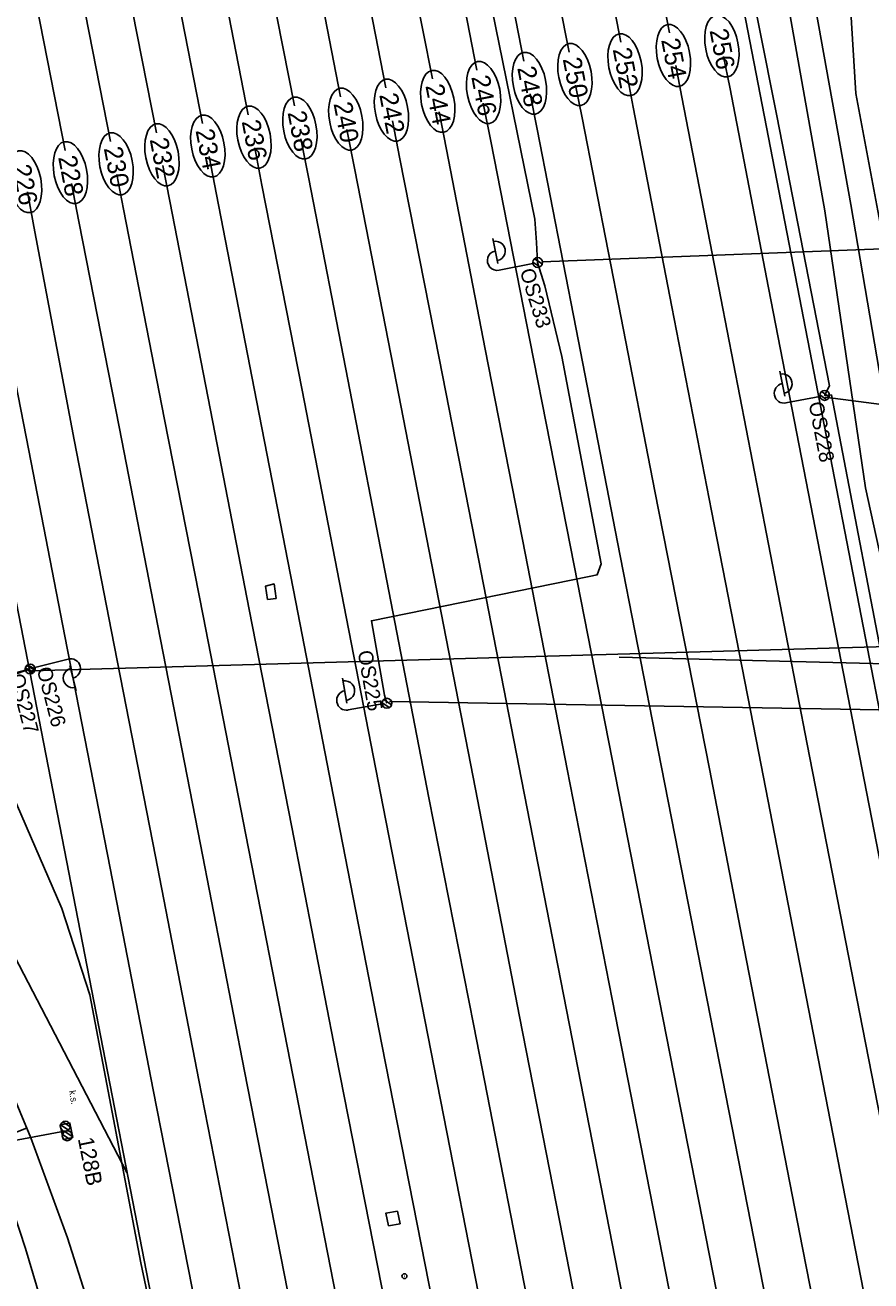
# Model space of a CAD drawing. Extents: x -545846 to -545044, y -1122650 to -1119108.
# Drawn here: x -545572.5 to -545486.4, y -1119708.7 to -1119580.9 of the extents above; entities that cross this region are included whole.
import ezdxf

# ---------------------------------------------------------------- set-up
doc = ezdxf.new("R2010")
doc.units = 0
for name, color, linetype in [('osvětlené plochy-hodnota-obrys', 7, 'Continuous'), ('Vrstva 1', 7, 'Continuous'), ('Vrstva 11 - Trakce', 7, 'Continuous'), ('Vrstva 12', 7, 'Continuous'), ('Vrstva 12 - Trakce zaklady', 7, 'Continuous'), ('Vrstva 25', 7, 'Continuous'), ('Vrstva 26', 7, 'Continuous'), ('Vrstva 50', 7, 'Continuous'), ('Vrstva 51', 7, 'Continuous'), ('Vrstva 62', 7, 'Continuous'), ('Vrstva 63', 7, 'Continuous'), ('Vrstva 7', 7, 'Continuous')]:
    doc.layers.add(name, color=color, linetype=linetype)

msp = doc.modelspace()

# ---------------------------------------------------------------- linework, layer by layer
at = {"layer": 'osvětlené plochy-hodnota-obrys'}
msp.add_line((-545562.16, -1119697.71), (-545631.88, -1119563.68), dxfattribs=at)
for points in [[(-545520.97, -1119506.47), (-545505.64, -1119546.72), (-545397.93, -1120102.85)], [(-545441.66, -1120319.91), (-545444.67, -1120302.28), (-545584.85, -1119581.02)]]:
    msp.add_lwpolyline(points, dxfattribs=at)
at = {"layer": 'Vrstva 1'}
for points in [[(-545561.97, -1119528.22), (-545559.49, -1119540.51), (-545556.23, -1119557.11), (-545552.77, -1119574.8), (-545549.8, -1119589.99)], [(-545557.89, -1119527.86), (-545555, -1119539.59), (-545551.52, -1119556.21), (-545548.07, -1119573.94), (-545545.11, -1119589.07)], [(-545566.49, -1119529.08), (-545564.1, -1119541.41), (-545560.85, -1119558.08), (-545557.41, -1119575.75), (-545554.45, -1119590.89)], [(-545571.21, -1119530.11), (-545568.88, -1119542.13), (-545565.56, -1119559.13), (-545562.1, -1119576.82), (-545559.16, -1119591.81)], [(-545575.84, -1119531.04), (-545573.5, -1119543.05), (-545570.17, -1119560.16), (-545566.74, -1119577.79), (-545563.84, -1119592.72)], [(-545580.39, -1119532.39), (-545578.14, -1119544.01), (-545574.96, -1119560.25), (-545571.36, -1119578.75), (-545568.45, -1119593.62)], [(-545518.71, -1119549.96), (-545514.79, -1119567.5), (-545511.88, -1119582.6)], [(-545513.79, -1119548.9), (-545509.85, -1119566.5), (-545506.91, -1119581.63)], [(-545523.93, -1119551.12), (-545520.1, -1119568.53), (-545517.13, -1119583.62)], [(-545528.32, -1119552.13), (-545524.69, -1119569.37), (-545521.75, -1119584.52)], [(-545537.98, -1119553.93), (-545533.98, -1119571.42), (-545531.04, -1119586.33)], [(-545533.4, -1119553.53), (-545529.46, -1119570.4), (-545526.52, -1119585.45)], [(-545542.57, -1119554.95), (-545538.71, -1119572.24), (-545535.78, -1119587.26)], [(-545547.17, -1119555.42), (-545543.32, -1119573.1), (-545540.4, -1119588.15)], [(-545501.4, -1119584.04), (-545500.78, -1119587.18), (-545496.82, -1119607.62), (-545492.98, -1119627.32), (-545488.03, -1119652.82), (-545482.44, -1119681.62), (-545479.01, -1119699.16)], [(-545506.26, -1119584.98), (-545505.64, -1119588.18), (-545501.7, -1119608.65), (-545497.83, -1119628.61), (-545492.89, -1119654.09), (-545487.27, -1119682.92), (-545483.88, -1119700.28)], [(-545516.47, -1119586.97), (-545515.81, -1119590.31), (-545511.83, -1119610.68), (-545508.39, -1119628.33), (-545502.85, -1119656.6), (-545499.31, -1119674.88), (-545493.36, -1119705.37)], [(-545511.23, -1119585.95), (-545510.6, -1119589.21), (-545506.66, -1119609.56), (-545502.65, -1119630.32), (-545497.81, -1119655), (-545492.27, -1119683.48), (-545488.74, -1119701.59)], [(-545521.1, -1119587.87), (-545520.4, -1119591.45), (-545516.42, -1119611.82), (-545512.19, -1119633.5), (-545508.07, -1119654.68), (-545504.04, -1119675.3)], [(-545530.38, -1119589.68), (-545529.62, -1119593.51), (-545525.67, -1119613.85), (-545521.59, -1119634.8), (-545517.32, -1119656.63), (-545512.75, -1119680.06)], [(-545525.87, -1119588.8), (-545525.11, -1119592.66), (-545521.12, -1119612.93), (-545516.99, -1119634), (-545512.76, -1119655.61), (-545508.3, -1119678.31)], [(-545535.12, -1119590.6), (-545534.37, -1119594.47), (-545530.38, -1119614.77), (-545526.36, -1119635.22), (-545521.97, -1119657.68), (-545517.39, -1119681.15)], [(-545539.75, -1119591.5), (-545538.95, -1119595.58), (-545534.97, -1119615.93), (-545531.13, -1119635.66), (-545526.67, -1119658.66), (-545522.17, -1119681.81)], [(-545549.15, -1119593.34), (-545548.41, -1119597.14), (-545544.33, -1119618.03), (-545540.3, -1119638.66), (-545536.06, -1119660.45), (-545531.51, -1119683.71)], [(-545544.45, -1119592.42), (-545543.65, -1119596.52), (-545539.68, -1119616.94), (-545535.68, -1119637.44), (-545531.4, -1119659.53), (-545526.85, -1119682.75)], [(-545553.79, -1119594.24), (-545553.04, -1119598.12), (-545548.95, -1119619.07), (-545544.95, -1119639.63), (-545540.7, -1119661.53), (-545536.19, -1119684.65)], [(-545563.19, -1119596.07), (-545562.5, -1119599.61), (-545558.32, -1119621.03), (-545554.39, -1119641.02), (-545550.04, -1119663.33), (-545545.54, -1119686.4)], [(-545558.51, -1119595.16), (-545557.8, -1119598.78), (-545553.65, -1119620.06), (-545549.7, -1119640.38), (-545545.38, -1119662.52), (-545540.87, -1119685.6)], [(-545567.8, -1119596.97), (-545567.04, -1119600.86), (-545562.92, -1119621.95), (-545559.02, -1119642.02), (-545554.68, -1119664.31), (-545550.17, -1119687.38)], [(-545572.28, -1119597.84), (-545571.63, -1119601.37), (-545567.52, -1119623.09), (-545563.72, -1119642.62), (-545559.26, -1119665.53), (-545554.82, -1119688.28)], [(-545577.12, -1119598.78), (-545576.45, -1119602.24), (-545572.16, -1119624.17), (-545568.47, -1119643.08), (-545563.87, -1119666.71), (-545559.47, -1119689.27)], [(-545588.23, -1119659.9), (-545581.76, -1119671.96), (-545577.41, -1119681.09), (-545571.95, -1119694.17)], [(-545504.04, -1119675.3), (-545496.76, -1119712.41), (-545491.63, -1119738.67), (-545486.65, -1119764.12), (-545480.23, -1119797.01), (-545475.32, -1119822.26), (-545468.39, -1119857.8), (-545462.99, -1119885.43), (-545456.77, -1119917.38), (-545451.56, -1119944.05), (-545446.59, -1119969.43), (-545441.08, -1119997.67), (-545435.96, -1120023.86), (-545430.59, -1120051.32), (-545426.85, -1120070.67)], [(-545508.3, -1119678.31), (-545501.41, -1119713.42), (-545496.34, -1119739.4), (-545491.32, -1119765.12), (-545484.91, -1119797.95), (-545479.98, -1119823.28), (-545473.04, -1119858.81), (-545467.63, -1119886.5), (-545461.42, -1119918.35), (-545456.18, -1119945.11), (-545451.23, -1119970.49), (-545445.73, -1119998.73), (-545440.63, -1120024.76), (-545435.23, -1120052.38), (-545431.51, -1120071.58)], [(-545512.75, -1119680.06), (-545506.04, -1119714.37), (-545500.99, -1119740.29), (-545495.97, -1119766.06), (-545489.56, -1119798.98), (-545484.63, -1119824.29), (-545477.72, -1119859.75), (-545472.31, -1119887.47), (-545466.08, -1119919.33), (-545460.87, -1119946.03), (-545455.91, -1119971.4), (-545450.38, -1119999.68), (-545445.29, -1120025.77), (-545439.89, -1120053.38), (-545436.18, -1120072.49)], [(-545522.17, -1119681.81), (-545515.38, -1119716.42), (-545510.35, -1119742.18), (-545505.33, -1119768), (-545498.9, -1119800.89), (-545493.99, -1119826.04), (-545487.08, -1119861.49), (-545481.61, -1119889.46), (-545475.38, -1119921.42), (-545470.2, -1119947.95), (-545465.28, -1119973.13), (-545459.72, -1120001.56), (-545454.6, -1120027.72), (-545449.19, -1120055.51), (-545445.53, -1120074.31)], [(-545517.39, -1119681.15), (-545510.7, -1119715.36), (-545505.65, -1119741.28), (-545500.67, -1119766.98), (-545494.24, -1119799.96), (-545489.36, -1119825.02), (-545482.41, -1119860.61), (-545476.97, -1119888.48), (-545470.74, -1119920.36), (-545465.53, -1119946.97), (-545460.61, -1119972.16), (-545455.05, -1120000.65), (-545449.96, -1120026.74), (-545444.56, -1120054.41), (-545440.88, -1120073.4)], [(-545526.85, -1119682.75), (-545520.07, -1119717.38), (-545515.03, -1119743.16), (-545509.97, -1119769.03), (-545503.62, -1119801.64), (-545498.65, -1119827.09), (-545491.8, -1119862.23), (-545486.29, -1119890.47), (-545480.04, -1119922.41), (-545474.85, -1119948.96), (-545469.96, -1119974), (-545464.39, -1120002.62), (-545459.33, -1120028.63), (-545453.88, -1120056.52), (-545450.25, -1120075.23)], [(-545531.51, -1119683.71), (-545524.75, -1119718.21), (-545519.66, -1119744.26), (-545514.65, -1119769.88), (-545508.26, -1119802.67), (-545503.31, -1119828.02), (-545496.43, -1119863.3), (-545490.98, -1119891.27), (-545484.71, -1119923.38), (-545479.52, -1119949.99), (-545474.63, -1119975.03), (-545469.04, -1120003.65), (-545463.99, -1120029.53), (-545458.53, -1120057.57), (-545454.92, -1120076.14)], [(-545540.87, -1119685.6), (-545534.1, -1119720.11), (-545529.03, -1119746.04), (-545524.03, -1119771.7), (-545517.65, -1119804.44), (-545512.65, -1119830.06), (-545505.8, -1119865.17), (-545500.3, -1119893.34), (-545494.1, -1119925.08), (-545488.85, -1119951.94), (-545483.92, -1119977.18), (-545478.37, -1120005.58), (-545473.32, -1120031.45), (-545467.8, -1120059.78), (-545464.26, -1120077.96)], [(-545536.19, -1119684.65), (-545529.41, -1119719.19), (-545524.32, -1119745.26), (-545519.36, -1119770.73), (-545512.98, -1119803.45), (-545508.01, -1119828.96), (-545501.11, -1119864.27), (-545495.65, -1119892.35), (-545489.42, -1119924.3), (-545484.2, -1119951), (-545479.29, -1119976.16), (-545473.71, -1120004.66), (-545468.64, -1120030.51), (-545463.14, -1120058.7), (-545459.58, -1120077.05)], [(-545545.54, -1119686.4), (-545538.77, -1119720.94), (-545533.66, -1119747.13), (-545528.69, -1119772.6), (-545522.29, -1119805.41), (-545517.29, -1119831.13), (-545510.48, -1119866), (-545504.93, -1119894.36), (-545498.77, -1119925.86), (-545493.48, -1119952.94), (-545488.61, -1119977.9), (-545482.96, -1120006.76), (-545477.96, -1120032.37), (-545472.41, -1120060.91), (-545468.91, -1120078.86)], [(-545550.17, -1119687.38), (-545543.44, -1119721.83), (-545538.34, -1119747.98), (-545533.33, -1119773.63), (-545526.95, -1119806.31), (-545521.9, -1119832.19), (-545515.14, -1119866.79), (-545509.58, -1119895.3), (-545503.43, -1119926.76), (-545498.13, -1119953.84), (-545493.24, -1119978.89), (-545487.6, -1120007.83), (-545482.64, -1120033.17), (-545477.04, -1120061.91), (-545473.58, -1120079.77)], [(-545559.47, -1119689.27), (-545552.78, -1119723.47), (-545547.74, -1119749.33), (-545542.64, -1119775.39), (-545536.2, -1119808.44), (-545530.73, -1119836.49), (-545524.44, -1119868.68), (-545518.8, -1119897.62), (-545512.95, -1119927.61), (-545507.41, -1119956), (-545503.72, -1119974.86), (-545496.87, -1120009.9), (-545493.13, -1120029.09), (-545486.04, -1120065.49), (-545482.9, -1120081.59)], [(-545554.82, -1119688.28), (-545548.1, -1119722.66), (-545543.03, -1119748.71), (-545538.01, -1119774.45), (-545531.59, -1119807.38), (-545526.53, -1119833.29), (-545519.82, -1119867.74), (-545514.23, -1119896.35), (-545508.11, -1119927.73), (-545502.81, -1119954.83), (-545497.92, -1119979.85), (-545492.2, -1120009.08), (-545487.31, -1120034.11), (-545481.69, -1120062.95), (-545478.25, -1120080.68)], [(-545571.95, -1119694.17), (-545568.22, -1119704.34), (-545564.14, -1119717.2), (-545561.89, -1119725.52), (-545559.37, -1119736.84), (-545556.44, -1119751.78), (-545552.48, -1119772.08), (-545548.81, -1119790.99), (-545544.91, -1119810.98), (-545541.19, -1119830.03), (-545537.15, -1119850.75), (-545533.37, -1119870.17), (-545529.25, -1119891.29), (-545525.41, -1119910.95), (-545521.61, -1119930.42), (-545517.59, -1119951), (-545514.11, -1119968.78), (-545510.93, -1119985.07), (-545507.19, -1120004.24), (-545504.36, -1120018.76), (-545500.38, -1120039.13), (-545497.15, -1120055.69), (-545493.47, -1120074.63), (-545491.78, -1120083.31)], [(-545575.65, -1119695.89), (-545572.47, -1119705.44), (-545569.61, -1119715.14), (-545566.65, -1119726.84), (-545564.33, -1119737.76), (-545561.4, -1119752.75), (-545557.46, -1119772.94), (-545553.77, -1119791.84), (-545549.8, -1119812.13), (-545546.09, -1119831.12), (-545541.98, -1119852.23), (-545537.99, -1119872.7), (-545534.14, -1119892.45), (-545530.37, -1119911.7), (-545526.48, -1119931.7), (-545522.7, -1119951.18), (-545519.05, -1119969.83), (-545515.88, -1119986.1), (-545512.2, -1120004.99), (-545509.4, -1120019.41), (-545505.37, -1120040.1), (-545502.14, -1120056.66), (-545498.43, -1120075.66), (-545496.75, -1120084.28)], [(-545488.74, -1119701.59), (-545481.88, -1119736.77), (-545476.93, -1119762.15), (-545470.57, -1119794.82), (-545465.63, -1119820.17), (-545458.72, -1119855.56), (-545453.29, -1119883.26), (-545447, -1119915.44), (-545441.82, -1119942.01), (-545436.87, -1119967.3), (-545431.4, -1119995.48), (-545426.21, -1120021.98), (-545420.91, -1120049.23), (-545417.12, -1120068.78)], [(-545493.36, -1119705.37), (-545486.99, -1119737.85), (-545482.07, -1119763.16), (-545475.68, -1119795.84), (-545470.7, -1119821.28), (-545463.79, -1119856.66), (-545458.35, -1119884.48), (-545452.09, -1119916.55), (-545446.9, -1119943.08), (-545441.96, -1119968.35), (-545436.44, -1119996.63), (-545431.34, -1120022.9), (-545425.98, -1120050.33), (-545422.21, -1120069.77)]]:
    msp.add_lwpolyline(points, dxfattribs=at)
for centre in [(-545506.51, -1119583.95), (-545501.58, -1119582.99), (-545511.44, -1119584.89), (-545516.54, -1119585.89), (-545525.84, -1119587.71), (-545521.17, -1119586.78), (-545530.51, -1119588.62), (-545539.87, -1119590.43), (-545535.22, -1119589.52), (-545544.55, -1119591.34), (-545549.22, -1119592.26), (-545558.59, -1119594.06), (-545553.92, -1119593.17), (-545563.26, -1119594.98), (-545572.58, -1119596.8), (-545567.91, -1119595.88)]:
    msp.add_ellipse(centre, major_axis=(0.61, -3.15), ratio=0.521067, dxfattribs=at)
at = {"layer": 'Vrstva 11 - Trakce'}
for p, q in [((-545568.91, -1119692.84), (-545568.13, -1119693.37)), ((-545568.68, -1119692.54), (-545567.94, -1119693.04)), ((-545594.64, -1119698.29), (-545568.34, -1119693.47)), ((-545568.72, -1119693.83), (-545567.93, -1119694.35)), ((-545568.49, -1119693.53), (-545567.75, -1119694.03))]:
    msp.add_line(p, q, dxfattribs=at)
for centre in [(-545568.44, -1119692.98), (-545568.24, -1119693.96)]:
    msp.add_circle(centre, 0.5, dxfattribs=at)
at = {"layer": 'Vrstva 12'}
for points in [[(-545546.95, -1119639.23), (-545547.84, -1119639.34), (-545548.04, -1119637.98), (-545547.17, -1119637.76)], [(-545535.51, -1119703.12), (-545535.78, -1119701.84), (-545534.61, -1119701.64), (-545534.35, -1119702.91)]]:
    msp.add_lwpolyline(points, close=True, dxfattribs=at)
at = {"layer": 'Vrstva 12 - Trakce zaklady'}
for p, q in [((-545567.97, -1119692.66), (-545568.95, -1119692.86)), ((-545567.68, -1119694.13), (-545568.66, -1119694.33))]:
    msp.add_line(p, q, dxfattribs=at)
for points in [[(-545568.66, -1119694.33), (-545568.95, -1119692.86), (-545567.97, -1119692.66), (-545567.68, -1119694.13), (-545568.66, -1119694.33)], [(-545567.97, -1119692.66), (-545567.97, -1119692.66), (-545567.68, -1119694.13), (-545567.68, -1119694.13)]]:
    msp.add_lwpolyline(points, dxfattribs=at)
at = {"layer": 'Vrstva 25'}
for p, q in [((-545524.4, -1119605.14), (-545524.91, -1119602.59)), ((-545520.1, -1119605.47), (-545520.83, -1119604.98)), ((-545519.86, -1119605.17), (-545520.66, -1119604.65)), ((-545520.83, -1119605.13), (-545524.26, -1119605.82)), ((-545495.18, -1119618.65), (-545495.68, -1119616.1)), ((-545491.61, -1119618.66), (-545495.05, -1119619.33)), ((-545490.89, -1119619.01), (-545491.62, -1119618.52)), ((-545490.65, -1119618.72), (-545491.44, -1119618.18)), ((-545572.27, -1119645.99), (-545571.51, -1119646.44)), ((-545571.52, -1119646.29), (-545568.14, -1119645.41)), ((-545572.49, -1119646.55), (-545575.88, -1119647.43)), ((-545571.75, -1119646.85), (-545572.5, -1119646.4)), ((-545572.49, -1119646.3), (-545571.67, -1119646.78)), ((-545571.52, -1119646.54), (-545572.35, -1119646.06)), ((-545567.96, -1119646.09), (-545567.31, -1119648.61)), ((-545539.75, -1119649.91), (-545540.21, -1119647.35)), ((-545535.22, -1119650.07), (-545536, -1119649.52)), ((-545536.18, -1119649.99), (-545539.63, -1119650.6)), ((-545535.47, -1119650.35), (-545536.19, -1119649.85))]:
    msp.add_line(p, q, dxfattribs=at)
for centre in [(-545520.34, -1119605.03), (-545520.34, -1119605.03), (-545491.12, -1119618.57), (-545491.12, -1119618.57), (-545572.01, -1119646.42), (-545572.01, -1119646.42), (-545572.01, -1119646.42), (-545572.01, -1119646.42), (-545535.69, -1119649.91), (-545535.69, -1119649.91)]:
    msp.add_circle(centre, 0.5, dxfattribs=at)
for centre, start, end in [((-545524.64, -1119603.86), 280.7798, 102.1849), ((-545524.46, -1119604.84), 101.4823, 281.4823), ((-545495.42, -1119617.37), 280.3732, 101.7783), ((-545495.24, -1119618.35), 101.0757, 281.0757), ((-545567.89, -1119646.38), 284.5653, 104.5653), ((-545567.65, -1119647.35), 103.8627, 285.2679), ((-545539.97, -1119648.63), 279.3145, 100.7196), ((-545539.8, -1119649.62), 100.017, 280.017)]:
    msp.add_arc(centre, 1, start, end, dxfattribs=at)
at = {"layer": 'Vrstva 26'}
for points in [[(-545534.52, -1119485.98), (-545528.13, -1119494.27), (-545519.61, -1119508.42), (-545513.14, -1119522.36), (-545513.6, -1119523.25), (-545512.74, -1119523.53), (-545509.96, -1119531.82), (-545503.87, -1119551.64), (-545499.84, -1119570.49), (-545500.17, -1119571.44), (-545499.66, -1119571.66), (-545495.99, -1119590.1), (-545490.61, -1119617.59), (-545491.12, -1119618.57), (-545490.42, -1119618.51), (-545484.14, -1119651.23)], [(-545535.69, -1119649.91), (-545535.92, -1119649.08), (-545537.26, -1119641.51), (-545515.1, -1119637.02), (-545514.27, -1119636.83), (-545513.88, -1119635.7), (-545517.88, -1119614.61), (-545519.61, -1119607.4), (-545520.34, -1119605.03), (-545520.44, -1119603), (-545520.63, -1119600.62), (-545525.34, -1119577.44)], [(-545537.26, -1119641.51), (-545515.1, -1119637.02)], [(-545557.86, -1119720.55), (-545560.74, -1119706.9), (-545565.92, -1119679.61), (-545568.8, -1119670.82), (-545576.09, -1119654.04), (-545578.2, -1119647.96), (-545573.23, -1119646.86), (-545572.01, -1119646.42)]]:
    msp.add_lwpolyline(points, dxfattribs=at)
at = {"layer": 'Vrstva 50'}
msp.add_line((-545533.93, -1119708.26), (-545533.88, -1119708.26), dxfattribs=at)
msp.add_circle((-545533.9, -1119708.26), 0.25, dxfattribs=at)
at = {"layer": 'Vrstva 51'}
for points in [[(-545511.73, -1119517.03), (-545497, -1119556.5), (-545492.54, -1119576.26), (-545488.43, -1119599.11), (-545483.62, -1119627.38), (-545478.79, -1119651.18), (-545474.99, -1119670.94), (-545470.7, -1119687.75)], [(-545514.46, -1119518.32), (-545500.04, -1119556.88), (-545495.23, -1119576.45), (-545491.1, -1119599.78), (-545486.96, -1119627.99), (-545481.75, -1119651.67), (-545478.35, -1119671.03), (-545474.36, -1119688.26)]]:
    msp.add_lwpolyline(points, dxfattribs=at)
at = {"layer": 'Vrstva 62'}
msp.add_lwpolyline([(-545497.33, -1119511.25), (-545486.34, -1119534.72), (-545495.96, -1119540.92), (-545493.16, -1119551.22), (-545484.39, -1119549.67), (-545482.18, -1119562.89), (-545489.11, -1119568.39), (-545487.95, -1119587.82), (-545483.04, -1119613.89), (-545473.08, -1119650.55), (-545465.95, -1119679.91), (-545460.34, -1119700)], dxfattribs=at)
at = {"layer": 'Vrstva 63'}
for p, q in [((-545471.67, -1119603.12), (-545519.87, -1119604.96)), ((-545468.42, -1119621.71), (-545491.06, -1119618.73)), ((-545464.14, -1119643.56), (-545571.89, -1119646.62)), ((-545459.08, -1119646.57), (-545512.02, -1119645.22)), ((-545462.3, -1119650.98), (-545535.41, -1119649.74))]:
    msp.add_line(p, q, dxfattribs=at)
at = {"layer": 'Vrstva 7'}
msp.add_line((-545576.11, -1119694.65), (-545572.37, -1119693.17), dxfattribs=at)

# ---------------------------------------------------------------- texts
at = {"layer": 'Vrstva 1'}
for s, p in [('256', (-545502.84, -1119581.4)), ('252', (-545512.7, -1119583.32)), ('254', (-545507.77, -1119582.36)), ('250', (-545517.79, -1119584.31)), ('248', (-545522.42, -1119585.21)), ('244', (-545531.77, -1119587.03)), ('246', (-545527.1, -1119586.13)), ('242', (-545536.47, -1119587.95)), ('238', (-545545.81, -1119589.76)), ('240', (-545541.13, -1119588.85)), ('236', (-545550.48, -1119590.67)), ('234', (-545555.18, -1119591.59)), ('230', (-545564.52, -1119593.4)), ('232', (-545559.85, -1119592.5)), ('228', (-545569.17, -1119594.31)), ('226', (-545573.84, -1119595.22))]:
    msp.add_text(s, height=1.875, rotation=280.9117, dxfattribs=at).set_placement(p)
at = {"layer": 'Vrstva 11 - Trakce'}
msp.add_text('128B', height=1.6, rotation=281.1975, dxfattribs=at).set_placement((-545567.16, -1119694.26))
at = {"layer": 'Vrstva 25'}
for s, rotation, p in [('OS233', 286.9804, (-545522.17, -1119605.88)), ('OS228', 280.8637, (-545492.75, -1119619.35)), ('OS225', 280.017, (-545538.67, -1119644.66)), ('OS227', 284.5653, (-545574.12, -1119647.11)), ('OS226', 284.5653, (-545571.35, -1119646.42))]:
    msp.add_text(s, height=1.5, rotation=rotation, dxfattribs=at).set_placement(p)
at = {"layer": 'Vrstva 63'}
msp.add_text('k.s.', height=0.688, rotation=279.922, dxfattribs=at).set_placement((-545568.06, -1119689.4))

doc.saveas('drawing.dxf')
